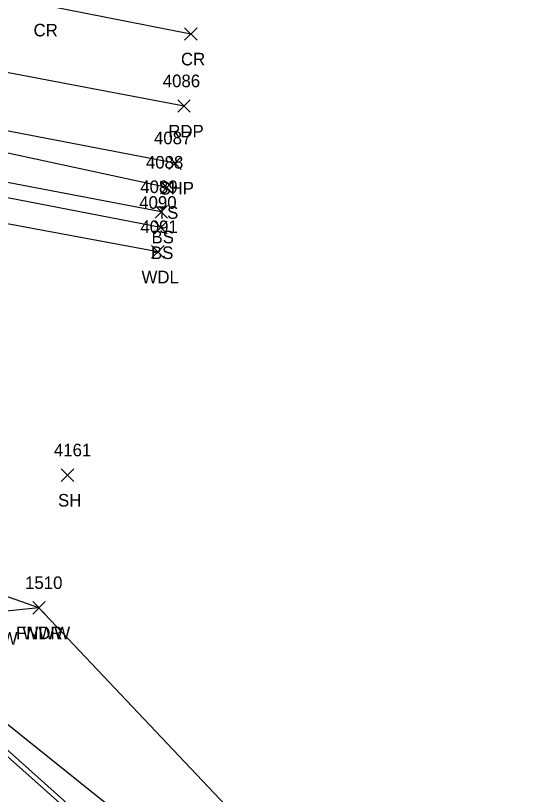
# Model space of a CAD drawing. Extents: x 1647574 to 1652703, y 212895 to 228670.
# Drawn here: x 1649279.8 to 1649361.4, y 226954.6 to 227078.5 of the extents above; entities that cross this region are included whole.
import ezdxf

# ---------------------------------------------------------------- set-up
doc = ezdxf.new("R2010")
doc.units = 0
for name, color, linetype in [('L_A', 7, 'Continuous'), ('L_I', 7, 'Continuous'), ('L_TIC', 7, 'Continuous'), ('LAWA', 7, 'Continuous'), ('LELB', 7, 'Continuous'), ('LFNC', 7, 'Continuous'), ('P_A', 7, 'Continuous'), ('P_I', 7, 'Continuous'), ('P_TIC', 7, 'Continuous'), ('PET', 7, 'Continuous'), ('PRC', 7, 'Continuous'), ('PSP', 7, 'Continuous'), ('RGR', 7, 'Continuous')]:
    doc.layers.add(name, color=color, linetype=linetype)

msp = doc.modelspace()

# ---------------------------------------------------------------- linework, layer by layer
at = {"layer": 'L_TIC'}
for points in [[(1649302.94, 227050.18), (1649304.94, 227052.18)], [(1649304.94, 227050.18), (1649302.94, 227052.18)], [(1649302.06, 227046.28), (1649304.06, 227048.28)], [(1649304.06, 227046.28), (1649302.06, 227048.28)], [(1649301.97, 227043.78), (1649303.97, 227045.78)], [(1649303.97, 227043.78), (1649301.97, 227045.78)], [(1649301.5, 227039.92), (1649303.5, 227041.92)], [(1649303.5, 227039.92), (1649301.5, 227041.92)], [(1649287.12, 227004.39), (1649289.12, 227006.39)], [(1649289.12, 227004.39), (1649287.12, 227006.39)], [(1649282.57, 226983.27), (1649284.57, 226985.27)], [(1649284.57, 226983.27), (1649282.57, 226985.27)], [(1649282.57, 226983.27), (1649284.57, 226985.27)], [(1649284.57, 226983.27), (1649282.57, 226985.27)]]:
    msp.add_lwpolyline(points, dxfattribs=at)
at = {"layer": 'LAWA'}
for points in [[(1649302.5, 227040.92), (1649260.46, 227048.73), (1649217.24, 227053.77), (1649243.37, 227014.39)], [(1649620.52, 226666.86), (1649581.67, 226703.66), (1649547.28, 226735.48), (1649514.21, 226767.75), (1649480.07, 226801.7), (1649444.95, 226835.57), (1649408.03, 226867.53), (1649382.09, 226894.12), (1649349.21, 226919.43), (1649317.07, 226948.87), (1649283.57, 226984.27), (1649262.7, 226991.58)]]:
    msp.add_lwpolyline(points, dxfattribs=at)
at = {"layer": 'LELB'}
for points in [[(1649303.94, 227051.18), (1649261.07, 227060.39), (1649216.61, 227069.45), (1649178.25, 227076.12), (1649140.52, 227081.32), (1649094.47, 227090.06), (1649051.01, 227097.65), (1649006.72, 227103.93), (1648958.76, 227112.58), (1648914.48, 227124.45), (1648876.09, 227132.2), (1648833.46, 227141.48), (1648786.83, 227153.43)], [(1649303.06, 227047.28), (1649260.98, 227055.31), (1649217.96, 227064.4), (1649177.85, 227072.42), (1649139.31, 227077.28), (1649094.12, 227086.64), (1649050.12, 227095.02), (1649005.65, 227100.61), (1648959.22, 227107.57), (1648919.51, 227113.25), (1648868.98, 227116.79), (1648831.48, 227119.83), (1648781.16, 227125.9)], [(1649302.97, 227044.78), (1649260.67, 227052.98), (1649215.1, 227059.72), (1649174.92, 227066.32), (1649138.43, 227073.45), (1649092.93, 227081.32), (1649048.99, 227090.42), (1649005.13, 227098.96), (1648958.86, 227104.77), (1648925.38, 227109.58), (1648868.51, 227114.83), (1648832.14, 227115.07)], [(1649611.68, 226660.43), (1649573.8, 226694.76), (1649539.29, 226728.48), (1649506.26, 226759.21), (1649471.69, 226791.64), (1649437.47, 226825.67), (1649400.06, 226860.66), (1649373.97, 226885.13), (1649343.06, 226911.31), (1649307.79, 226942.26), (1649266.92, 226975.01), (1649262.13, 226979.91), (1649252.93, 226990.96)]]:
    msp.add_lwpolyline(points, dxfattribs=at)
at = {"layer": 'LFNC'}
msp.add_lwpolyline([(1649283.57, 226984.27), (1649275.2, 226983.4)], dxfattribs=at)
at = {"layer": 'P_TIC'}
for points in [[(1649306.76, 227074.6), (1649308.76, 227076.6)], [(1649308.76, 227074.6), (1649306.76, 227076.6)], [(1649305.68, 227063.13), (1649307.68, 227065.13)], [(1649307.68, 227063.13), (1649305.68, 227065.13)], [(1649304.23, 227054.05), (1649306.23, 227056.05)], [(1649306.23, 227054.05), (1649304.23, 227056.05)]]:
    msp.add_lwpolyline(points, dxfattribs=at)
at = {"layer": 'PET'}
msp.add_lwpolyline([(1649306.68, 227064.13), (1649262.99, 227072.36), (1649217.79, 227081.09), (1649180.88, 227089.3), (1649143.91, 227096.66), (1649097.06, 227105.07), (1649054.53, 227112.89), (1649010.67, 227121.22), (1648964.11, 227130.39), (1648922.42, 227138.03), (1648885.03, 227145.38), (1648836.17, 227155.58), (1648791.11, 227166.69)], dxfattribs=at)
at = {"layer": 'PRC'}
msp.add_lwpolyline([(1648578.47, 227245.09), (1648614.14, 227232.38), (1648658.38, 227217.21), (1648693.17, 227205.45), (1648728.77, 227194.61), (1648764.16, 227184.6), (1648791.48, 227177.33), (1648822.26, 227169.58), (1648868.21, 227159.38), (1648902.01, 227152.53), (1648938.68, 227144.92), (1648979.68, 227137.48), (1649011.64, 227131.5), (1649049.01, 227124.37), (1649090.36, 227116.95), (1649126.94, 227110.35), (1649164.15, 227103.49), (1649199.47, 227096.77), (1649251.63, 227086.36), (1649284.28, 227080.21), (1649307.76, 227075.6)], dxfattribs=at)
at = {"layer": 'PSP'}
for points in [[(1649305.23, 227055.05), (1649261.49, 227063.44), (1649216.57, 227072.89), (1649179.12, 227080.23), (1649141.32, 227088.23), (1649095.57, 227096.47), (1649052.89, 227104.28), (1649009.15, 227112.65), (1648960.8, 227122.11), (1648921.9, 227129.09), (1648883.47, 227136.6), (1648833.93, 227146.38), (1648787.9, 227157.82)], [(1649606.95, 226655.87), (1649570.92, 226690.01), (1649534.66, 226724.21), (1649502.87, 226754.78), (1649467.98, 226787.83), (1649433.22, 226820.15), (1649395.45, 226855.86), (1649369.29, 226880.34), (1649338.69, 226908.03), (1649304.51, 226937.47), (1649274.58, 226964.09), (1649261.77, 226975.07), (1649262.11, 226976.25), (1649259.14, 226977.14), (1649257.68, 226977.62), (1649243.4, 226991.01), (1649239.83, 226990.77), (1649218.05, 226994.51), (1649195.64, 226998.51), (1649190.94, 226999.11)]]:
    msp.add_lwpolyline(points, dxfattribs=at)
at = {"layer": 'RGR'}
msp.add_lwpolyline([(1649607.54, 226656.38), (1649571.29, 226690.65), (1649535.2, 226725), (1649503.13, 226755.54), (1649468.46, 226788.77), (1649433.73, 226820.87), (1649396.03, 226856.51), (1649370.04, 226881.22), (1649339.35, 226908.59), (1649304.93, 226938.03), (1649276.23, 226963.71), (1649262.11, 226976.25)], dxfattribs=at)

# ---------------------------------------------------------------- texts
at = {"layer": 'L_A'}
for s, p in [('TS', (1649302.35, 227046.18)), ('BS', (1649301.5, 227042.28)), ('BS', (1649301.41, 227039.78)), ('WDL', (1649299.91, 227035.92)), ('SH', (1649286.61, 227000.39)), ('FNWW', (1649271.55, 226978.4)), ('FNWW', (1649279.92, 226979.27)), ('WDR', (1649280.94, 226979.27))]:
    msp.add_text(s, height=2, dxfattribs=at).set_placement(p)
at = {"layer": 'L_I'}
for s, p in [('4088', (1649300.61, 227054.18)), ('4089', (1649299.71, 227050.28)), ('4090', (1649299.54, 227047.78)), ('4091', (1649299.73, 227043.92)), ('4161', (1649285.95, 227008.39)), ('1510', (1649281.36, 226987.27)), ('1510', (1649281.36, 226987.27))]:
    msp.add_text(s, height=2, dxfattribs=at).set_placement(p)
at = {"layer": 'P_A'}
for s, p in [('CR', (1649282.71, 227075.21)), ('CR', (1649306.19, 227070.6)), ('RDP', (1649304.17, 227059.13)), ('SHP', (1649302.76, 227050.05))]:
    msp.add_text(s, height=2, dxfattribs=at).set_placement(p)
at = {"layer": 'P_I'}
for s, p in [('4086', (1649303.29, 227067.13)), ('4087', (1649301.89, 227058.05))]:
    msp.add_text(s, height=2, dxfattribs=at).set_placement(p)

doc.saveas('drawing.dxf')
